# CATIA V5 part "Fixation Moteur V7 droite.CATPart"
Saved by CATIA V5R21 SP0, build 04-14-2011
Part number: MOTEURDROIT
Bounding box of the stored display mesh (mm): x -4.2 to 4.2, y -40 to 0, z -20 to 40
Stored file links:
  C:\Users\2027.DESARCY-LEMIE30\Desktop\V14(17.02.2023)\Fixation Moteur V7 droite.CATPart
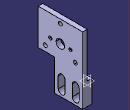
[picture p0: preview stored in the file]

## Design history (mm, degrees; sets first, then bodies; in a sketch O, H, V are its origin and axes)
Body1 (main body)
  Sketch1 on yz-plane, origin (0, 0, 0), H (0, 1, 0), V (0, 0, 1)
    line L1 (-40, 40) -> (0, 40)
    line L2 (0, 40) -> (0, 0)
    line L3 (0, 0) -> (-40, 0)
    line L4 (-40, 0) -> (-40, 40)
    point P3 (0, 0)
    length L4 = 40
    length L1 = 40
    horizontal: L1 H, L3 H
    vertical: L2 V, L4 V
    coincidence: P3 O
  Pad1: profile Sketch1, direction (1, 0, 0), length 4.2
  Sketch2 on end face of Pad1, origin (4.2, 0, 0), H (0, 1, 0), V (0, 0, 1)
    line L1 (-25, 0) -> (0, 0)
    line L2 (0, 0) -> (0, -20)
    line L3 (0, -20) -> (-25, -20)
    line L4 (-25, -20) -> (-25, 0)
    point P2 (0, 0)
    length L2 = 20
    length L3 = 25
    horizontal: L1 H, L3 H
    vertical: L2 V, L4 V
    coincidence: P2 O
  Pad2: profile Sketch2, direction (-1, 0, 0), length 8.4
  Sketch3 on end face of Pad2, origin (-4.2, 0, 0), H (0, -1, 0), V (0, 0, 1)
    point P1 (3.15, -5)
    line L1 (9.35, -5) -> (9.35, -15)
    line L2 (3.15, -15) -> (3.15, -5)
    point P2 (9.35, -5)
    point P3 (9.35, -15)
    point P4 (3.15, -15)
    axis line L3 (12.5, 2.3624) -> (12.5, -21.6714)
    reference projected line E1 (25, 0) -> (25, -20) from edge [end face of Pad2 | face of Pad2 from Sketch2.L4]
    arc A1 centre (6.25, -5) radius 3.1 from (9.35, -5) to (3.15, -5) ccw
    point P8 (10.7649, -15.4491)
    arc A2 centre (6.25, -15) radius 3.1 from (3.15, -15) to (9.35, -15) ccw
    point P9 (6.25, -15)
    point P10 (3.15, -15)
    point P11 (9.35, -15)
    point P12 (21.85, -5)
    point P13 (21.85, -15)
    line L4 (21.85, -15) -> (21.85, -5)
    point P14 (15.65, -5)
    arc A3 centre (18.75, -5) radius 3.1 from (15.65, -5) to (21.85, -5) cw
    point P16 (15.65, -15)
    line L5 (15.65, -5) -> (15.65, -15)
    point P17 (15.65, -15)
    point P18 (21.85, -15)
    point P19 (18.75, -15)
    arc A4 centre (18.75, -15) radius 3.1 from (21.85, -15) to (15.65, -15) cw
    reference projected line E2 (25, -20) -> (0, -20) from edge [end face of Pad2 | face of Pad2 from Sketch2.L3]
    distance L3 E1 = 12.5
    radius A1 = 3.1
    distance P9 P19 = 12.5
    length L4 = 10
    distance A4 E2 = 1.9
    vertical: L1 V, L2 V, L3 V
    tangency: A1 L1, A1 L2, A2 L1, A2 L2
    coincidence: P4 A2, L1 P11, L2 P10, P3 P11, P4 P10, P13 P18, P16 P17
    symmetry: P1 P12 L3, P4 P13 L3, L2 L4 L3, P2 P14 L3, A1 A3 L3, P3 P16 L3, L1 L5 L3, P11 P17 L3, P10 P18 L3, A2 A4 L3
  Pocket1: profile Sketch3, direction (1, 0, 0), through (limit type 3)
  Sketch4 on start face of Pad1, origin (0, 0, 0), H (0, -1, 0), V (0, 0, 1)
    construction line L1 (0, 20.75) -> (40, 20.75)
    point P1 (0, 20.75)
    point P2 (40, 20.75)
    reference projected line E1 (0, 40) -> (40, 40) from edge [start face of Pad1 | face of Pad1 from Sketch1.L1]
    reference projected line E2 (0, 0) -> (0, 40) from edge [start face of Pad1 | face of Pad2]
    reference projected line E3 (40, 40) -> (40, 0) from edge [start face of Pad1 | face of Pad1 from Sketch1.L4]
    construction line L2 (20, 40) -> (20, 0)
    point P3 (20, 40)
    point P4 (20, 0)
    reference projected line E4 (0, 40) -> (40, 40) from edge [start face of Pad1 | face of Pad1 from Sketch1.L1]
    reference projected line E5 (40, 0) -> (0, 0) from edge [start face of Pad1 | face of Pad1 from Sketch1.L3]
    reference projected line E6 (40, 40) -> (40, 0) from edge [start face of Pad1 | face of Pad1 from Sketch1.L4]
    circle A1 centre (20, 20.75) radius 4
    point P5 (20, 20.75)
    construction line L3 (20, 20.75) -> (0, 9.203)
    point P6 (0, 9.203)
    axis line L4 (20, 20.75) -> (40, 9.203)
    point P7 (40, 9.203)
    reference projected line E7 (40, 40) -> (40, 0) from edge [start face of Pad1 | face of Pad1 from Sketch1.L4]
    circle A2 centre (20, 36.3385) radius 1.75
    point P8 (20, 36.3385)
    point P9 (33.5, 12.9558)
    circle A3 centre (33.5, 12.9558) radius 1.75
    point P10 (6.5, 12.9558)
    circle A4 centre (6.5, 12.9558) radius 1.75
    distance E1 L1 = 19.25
    distance L2 E6 = 20
    radius A1 = 4
    angle L3 L2 = 120
    angle L2 L4 = 120
    radius A2 = 1.75
    distance P9 P10 = 27
    coincidence: P1 E2, P2 E3, E4 P3, P4 E5, P6 V, P7 E7, P8 L2, P5 L1, P5 L2
    vertical: L2 V
    symmetry: A2 A3 L3, A3 A4 L2
  Pocket2: profile Sketch4, direction (1, 0, 0), through (limit type 3)
  Sketch5 on start face of Pad1, origin (0, 0, 0), H (0, -1, 0), V (0, 0, 1)
    point P1 (40, 0)
    line L1 (40, 0) -> (25, 0)
    line L2 (25, 0) -> (25, 8)
    line L3 (25, 8) -> (40, 8)
    line L4 (40, 8) -> (40, 0)
    reference projected line E1 (0, -20) -> (0, 0) from edge [end face of Pad2 | face of Pad2 from Sketch2.L2]
    reference projected line E2 (25, 0) -> (25, -20) from edge [end face of Pad2 | face of Pad2 from Sketch2.L4]
    reference projected point E3 (40, 0) from vertex [face of Pad1 from Sketch1.L3 | start face of Pad1 | face of Pad1 from Sketch1.L4]
    length L2 = 8
    length L3 = 15
    distance E1 E2 = 25 (reference)
    horizontal: L1 H, L3 H
    vertical: L2 V, L4 V
    coincidence: P1 E3
  Pocket3: profile Sketch5, direction (1, 0, 0), through (limit type 3)
  Sketch6 on start face of Pad1, origin (0, -33.8289, 21.1001), H (0, 1, 0), V (0, 0, -1)
    point P1 (22.8289, 0.3501)
    axis line L1 (13.8289, 0.3501) -> (40.6944, 0.3501)
    point P2 (13.8289, 0.3501)
    reference projected circle E1 centre (13.8289, 0.3501) radius 4 from edge [start face of Pad1 | face of Pocket2 from Sketch4.A1]
    reference projected circle E2 centre (13.8289, 0.3501) radius 4 from edge [start face of Pad1 | face of Pocket2 from Sketch4.A1]
    distance P1 E2 = 5
    horizontal: L1 H
    concentricity: P2 E1
    coincidence: P1 L1
  Hole1: placed by Sketch6, at (0, -11, 20.75) direction (1, 0, 0), diameter 3, through (limit type 6), counterbore diameter 6, counterbore depth 3
  RectPattern1: of Hole1, direction 1 instances 2, spacing 18, along face of Pad1 from Sketch1.L1 reversed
